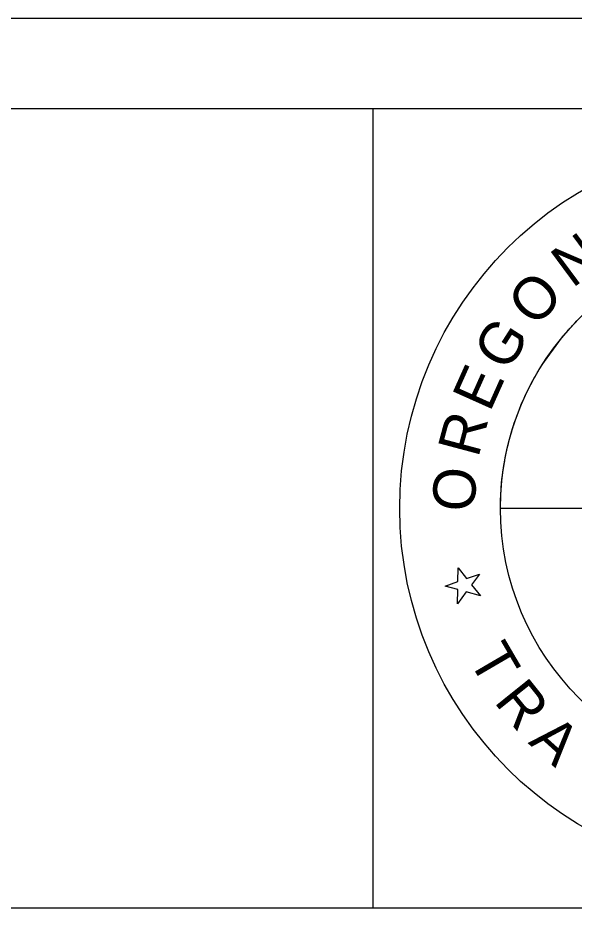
# Model space of a CAD drawing. Extents: x 0 to 1.42, y 0 to 0.92.
# Drawn here: x 1.3176 to 1.3554, y 0.1613 to 0.2228 of the extents above; entities that cross this region are included whole.
import ezdxf

# ---------------------------------------------------------------- set-up
doc = ezdxf.new("R2010")
doc.units = 0
doc.layers.add('P_ODOT_PLAN_General', color=7, linetype='Continuous')
doc.layers.add('P_ODOT_PLAN_TBlock', color=7, linetype='Continuous')

msp = doc.modelspace()

# ---------------------------------------------------------------- linework, layer by layer
at = {"layer": 'P_ODOT_PLAN_General'}
msp.add_lwpolyline([(1.395867, 0.041667), (0.889038, 0.041667), (0.889038, 0.222823), (1.395867, 0.222823)], close=True, dxfattribs=at)
at = {"layer": 'P_ODOT_PLAN_TBlock'}
for p, q in [((1.3417, 0.1625), (1.3417, 0.216667)), ((1.120878, 0.1625), (1.395867, 0.1625))]:
    msp.add_line(p, q, dxfattribs=at)
for points in [[(0.958367, 0.041667), (1.395867, 0.041667), (1.395867, 0.216667), (0.958367, 0.216667)], [(1.346572, 0.18432), (1.347434, 0.184617), (1.347446, 0.185551), (1.348031, 0.184822), (1.348892, 0.185119), (1.348366, 0.184404), (1.348971, 0.183649), (1.348008, 0.183918), (1.347415, 0.183113), (1.347427, 0.184081)]]:
    msp.add_lwpolyline(points, close=True, dxfattribs=at)
msp.add_lwpolyline([(1.356994, 0.189583), (1.35032, 0.189583), (1.35032, 0.189645), (1.35032, 0.18976), (1.350331, 0.190204), (1.350339, 0.190414), (1.350372, 0.190984), (1.350426, 0.191564), (1.350434, 0.191675), (1.350514, 0.192229), (1.350521, 0.192275), (1.350521, 0.192276), (1.350521, 0.192281), (1.350532, 0.19235), (1.350544, 0.192424), (1.350568, 0.192571), (1.350586, 0.192675), (1.350615, 0.192841), (1.350646, 0.193006), (1.350687, 0.193214), (1.350735, 0.193444), (1.350787, 0.193675), (1.350861, 0.193985), (1.350909, 0.194171), (1.350977, 0.194425), (1.351043, 0.194657), (1.351086, 0.194803), (1.351086, 0.194803), (1.351088, 0.194811), (1.351096, 0.194837), (1.351161, 0.195047), (1.351263, 0.19536), (1.351383, 0.195708), (1.351514, 0.196059), (1.35161, 0.196307), (1.351668, 0.196451), (1.351677, 0.196474), (1.351685, 0.196493), (1.351691, 0.196508), (1.351694, 0.196516), (1.351695, 0.196517), (1.351698, 0.196524), (1.35171, 0.196555), (1.351737, 0.196619), (1.351871, 0.19693), (1.351944, 0.197092), (1.351985, 0.197179), (1.352008, 0.197233), (1.352098, 0.197423), (1.352216, 0.197666), (1.35238, 0.197988), (1.352529, 0.198269), (1.352615, 0.198424), (1.352644, 0.198475), (1.352785, 0.198723), (1.352839, 0.198815), (1.352898, 0.198915), (1.352978, 0.199046), (1.35305, 0.199164), (1.353131, 0.199294), (1.354459, 0.201131), (1.354546, 0.201236), (1.354623, 0.201328), (1.3548, 0.201533), (1.354848, 0.201588), (1.354943, 0.201696), (1.354975, 0.201731), (1.355126, 0.201898), (1.355197, 0.201974), (1.355219, 0.201997), (1.355336, 0.202122), (1.355506, 0.202297)], dxfattribs=at)
for radius in [0.025, 0.018179]:
    msp.add_circle((1.368499, 0.189583), radius, dxfattribs=at)

# ---------------------------------------------------------------- texts
for s, rotation, p in [('N', 36.51883, (1.35519, 0.204478)), ('O', 47.07924, (1.352685, 0.201786)), ('G', 57.37401, (1.350759, 0.198763)), ('E', 65.85625, (1.349599, 0.196046)), ('R', 75.01818, (1.348811, 0.192955)), ('O', 85.57859, (1.348527, 0.189289)), ('T', 300.27437, (1.348099, 0.179384)), ('R', 308.78004, (1.349832, 0.176479)), ('A', 317.94197, (1.352157, 0.173674))]:
    msp.add_text(s, height=0.002869, rotation=rotation, dxfattribs=at).set_placement(p)

doc.saveas('drawing.dxf')
